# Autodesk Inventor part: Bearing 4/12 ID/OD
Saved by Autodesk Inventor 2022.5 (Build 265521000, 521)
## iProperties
Created: 2025-01
Part Number: Bearing 4/12 ID/OD
Material: Generic
Document SubType Name: Modeling
Designer: AdminForWorker
Density: 1 g/cm^3
Appearance: Default
Title: Bearing 4/12 ID/OD v1
Author: AdminForWorker
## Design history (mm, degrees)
feature "Body1"
body "Solid1"
